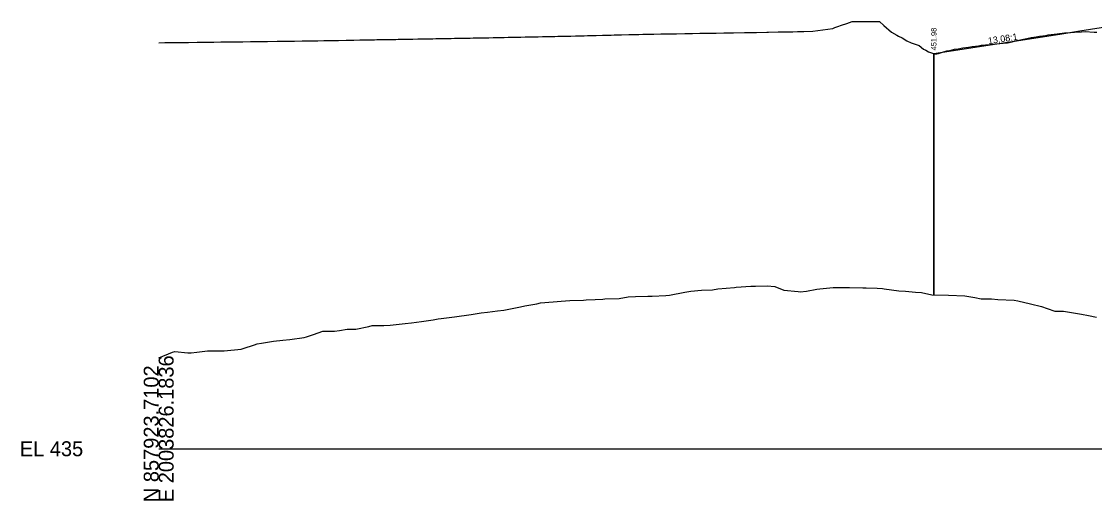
# Model space of a CAD drawing. Extents: x 2058594 to 2062449, y 841632 to 858028.
# Drawn here: x 2060920.8 to 2061121.7, y 856203.8 to 856293.5 of the extents above; entities that cross this region are included whole.
import ezdxf

# ---------------------------------------------------------------- set-up
doc = ezdxf.new("R2010")
doc.units = 0
for name, color, linetype in [('RD_DDB_Profile_Elev', 7, 'Continuous'), ('RD_GPK_XS_Cell', 7, 'Continuous'), ('RD_XS_EarthShd', 7, 'Continuous'), ('RD_XS_EwShp1', 7, 'Continuous'), ('RD_XS_ExGround', 7, 'Continuous'), ('RD_XS_MatchLine', 7, 'Continuous'), ('RD_XS_TieSlope', 7, 'Continuous'), ('RD_XS_TX_Ditch', 7, 'Continuous'), ('RD_XS_TX_Slope', 7, 'Continuous')]:
    doc.layers.add(name, color=color, linetype=linetype)

msp = doc.modelspace()

# ---------------------------------------------------------------- linework, layer by layer
at = {"layer": 'RD_DDB_Profile_Elev'}
msp.add_lwpolyline([(2060946.51, 856289.54), (2060947.67, 856289.56), (2060949.01, 856289.57), (2060950.54, 856289.59), (2060952.1, 856289.61), (2060953.74, 856289.63), (2060955.31, 856289.65), (2060956.81, 856289.67), (2060958.17, 856289.69), (2060959.34, 856289.7), (2060960.12, 856289.71), (2060961.06, 856289.72), (2060962.27, 856289.74), (2060963.68, 856289.75), (2060965.21, 856289.77), (2060966.89, 856289.79), (2060968.71, 856289.82), (2060970.37, 856289.84), (2060971.95, 856289.86), (2060973.39, 856289.88), (2060974.35, 856289.89), (2060975.33, 856289.9), (2060976.28, 856289.92), (2060977.42, 856289.94), (2060978.67, 856289.96), (2060980.16, 856289.99), (2060981.58, 856290.01), (2060982.73, 856290.03), (2060983.06, 856290.04), (2060984.16, 856290.06), (2060984.55, 856290.07), (2060985.57, 856290.09), (2060986, 856290.09), (2060986.91, 856290.11), (2060987.36, 856290.12), (2060988.12, 856290.13), (2060988.58, 856290.14), (2060989.15, 856290.15), (2060989.72, 856290.16), (2060990.18, 856290.17), (2060990.91, 856290.18), (2060991.33, 856290.19), (2060992.18, 856290.2), (2060992.55, 856290.21), (2060994.07, 856290.24), (2060995.04, 856290.25), (2060995.44, 856290.26), (2060996.4, 856290.28), (2060996.89, 856290.29), (2060997.82, 856290.3), (2060998.38, 856290.31), (2060999.24, 856290.33), (2060999.86, 856290.34), (2061000.61, 856290.35), (2061001.27, 856290.36), (2061001.89, 856290.37), (2061002.37, 856290.38), (2061003.03, 856290.39), (2061003.51, 856290.4), (2061004.16, 856290.41), (2061004.8, 856290.43), (2061005.39, 856290.44), (2061006.15, 856290.45), (2061006.66, 856290.46), (2061007.49, 856290.47), (2061007.89, 856290.48), (2061008.29, 856290.49), (2061009.15, 856290.5), (2061009.69, 856290.52), (2061010.35, 856290.53), (2061011.19, 856290.54), (2061011.94, 856290.56), (2061012.74, 856290.57), (2061013.56, 856290.59), (2061014.29, 856290.6), (2061015.15, 856290.62), (2061015.78, 856290.63), (2061016.64, 856290.65), (2061017.15, 856290.66), (2061017.53, 856290.67), (2061018.36, 856290.69), (2061018.73, 856290.7), (2061019.51, 856290.71), (2061020, 856290.72), (2061020.67, 856290.74), (2061021.25, 856290.75), (2061021.76, 856290.76), (2061022.3, 856290.77), (2061022.92, 856290.79), (2061023.64, 856290.8), (2061024.55, 856290.83), (2061025.15, 856290.84), (2061026.19, 856290.86), (2061026.76, 856290.88), (2061027.89, 856290.91), (2061028.4, 856290.92), (2061029.59, 856290.95), (2061030.01, 856290.96), (2061031.21, 856290.99), (2061031.77, 856291), (2061033.16, 856291.03), (2061034.55, 856291.07), (2061035.73, 856291.1), (2061036.42, 856291.11), (2061037.12, 856291.12), (2061038.06, 856291.14), (2061039.21, 856291.16), (2061040.53, 856291.18), (2061041.96, 856291.21), (2061043.47, 856291.23), (2061044.99, 856291.26), (2061046.46, 856291.28), (2061047.82, 856291.31), (2061048.99, 856291.32), (2061049.89, 856291.34), (2061050.88, 856291.36), (2061052.3, 856291.38), (2061054.09, 856291.42), (2061056.17, 856291.45), (2061058.44, 856291.49), (2061060.36, 856291.53), (2061060.69, 856291.53), (2061062.46, 856291.56), (2061064, 856291.59), (2061065.24, 856291.61), (2061066.09, 856291.62), (2061066.49, 856291.63), (2061066.8, 856291.64), (2061067.28, 856291.65), (2061069, 856291.68), (2061072.74, 856292.23), (2061073.11, 856292.37), (2061073.63, 856292.56), (2061074.36, 856292.82), (2061075.32, 856293.16), (2061076.34, 856293.53), (2061077.13, 856293.53), (2061077.48, 856293.53), (2061078.43, 856293.53), (2061079.12, 856293.53), (2061079.74, 856293.53), (2061080.64, 856293.53), (2061081.43, 856293.53), (2061082.27, 856292.74), (2061083.72, 856291.53), (2061084.69, 856290.98), (2061085.01, 856290.8), (2061085.67, 856290.44), (2061086.6, 856289.93), (2061087.36, 856289.53), (2061087.74, 856289.41), (2061088.89, 856289.01), (2061089.69, 856288.37), (2061090.15, 856288.13), (2061090.6, 856287.87), (2061091.74, 856287.44), (2061092.19, 856287.48), (2061092.52, 856287.53), (2061093.05, 856287.69), (2061094.08, 856288.01), (2061094.45, 856288.05), (2061095.48, 856288.33), (2061096.19, 856288.41), (2061097.08, 856288.62), (2061098.09, 856288.72), (2061098.77, 856288.86), (2061100.01, 856288.97), (2061100.47, 856289.06), (2061102.08, 856289.22), (2061103.37, 856289.33), (2061104.61, 856289.44), (2061105.44, 856289.53), (2061106.29, 856289.72), (2061107.18, 856289.96), (2061107.52, 856290.01), (2061108.43, 856290.24), (2061109.05, 856290.32), (2061109.86, 856290.52), (2061110.78, 856290.63), (2061111.42, 856290.77), (2061112.59, 856290.91), (2061113.02, 856291), (2061114.74, 856291.22), (2061116.09, 856291.37), (2061117.2, 856291.47), (2061117.96, 856291.53), (2061119.26, 856291.59), (2061119.96, 856291.65), (2061121.63, 856291.53), (2061122.12, 856291.53)], dxfattribs=at)
at = {"layer": 'RD_GPK_XS_Cell'}
msp.add_line((2060946.51, 856213.53), (2061196.51, 856213.53), dxfattribs=at)
at = {"layer": 'RD_XS_EarthShd'}
msp.add_line((2061124.96, 856292.65), (2061118.96, 856291.69), dxfattribs=at)
at = {"layer": 'RD_XS_EwShp1'}
for p, q in [((2061118.96, 856291.69), (2061115.21, 856291.09)), ((2061124.96, 856292.65), (2061118.96, 856291.69)), ((2061115.21, 856291.09), (2061091.62, 856287.48)), ((2061091.62, 856287.48), (2061091.62, 856242.33))]:
    msp.add_line(p, q, dxfattribs=at)
at = {"layer": 'RD_XS_ExGround'}
msp.add_lwpolyline([(2060946.51, 856230.55), (2060949.11, 856231.6), (2060949.52, 856231.75), (2060951.94, 856231.46), (2060952.6, 856231.5), (2060953.66, 856231.6), (2060955.68, 856231.89), (2060957.68, 856231.88), (2060958.76, 856231.89), (2060961.93, 856232.18), (2060962.3, 856232.32), (2060964.43, 856232.99), (2060964.93, 856233.16), (2060965.73, 856233.32), (2060968.01, 856233.7), (2060969.75, 856233.86), (2060971.09, 856234.01), (2060973.77, 856234.38), (2060974.17, 856234.46), (2060975.49, 856234.94), (2060977.25, 856235.55), (2060979.41, 856235.53), (2060980.33, 856235.64), (2060981.81, 856235.92), (2060983.41, 856235.92), (2060985.83, 856236.39), (2060986.49, 856236.59), (2060988.68, 856236.62), (2060989.85, 856236.65), (2060992.66, 856236.96), (2060993.87, 856237.11), (2060995.74, 856237.34), (2060997.89, 856237.64), (2060998.82, 856237.84), (2060999.4, 856237.91), (2061001.91, 856238.25), (2061004.98, 856238.69), (2061006.89, 856238.95), (2061008.06, 856239.08), (2061009.95, 856239.33), (2061011.15, 856239.49), (2061014.23, 856240.09), (2061015.05, 856240.27), (2061017.31, 856240.69), (2061018, 856240.83), (2061020.39, 856241.01), (2061021.88, 856241.14), (2061023.47, 856241.29), (2061026.04, 856241.33), (2061026.55, 856241.39), (2061028.24, 856241.45), (2061029.63, 856241.54), (2061030.06, 856241.58), (2061032.72, 856241.67), (2061034.37, 856241.95), (2061035.8, 856242.06), (2061038.1, 856242.09), (2061038.88, 856242.08), (2061041.43, 856242.23), (2061042.12, 856242.28), (2061045.04, 856242.82), (2061046.14, 856243.02), (2061048.12, 856243.19), (2061050.16, 856243.31), (2061051.2, 856243.49), (2061054.28, 856243.73), (2061054.61, 856243.76), (2061057.37, 856243.97), (2061058.21, 856243.99), (2061060.45, 856244.06), (2061061.84, 856243.89), (2061063.53, 856243.23), (2061066.25, 856242.95), (2061066.61, 856242.91), (2061067.8, 856243.06), (2061069.69, 856243.4), (2061070.27, 856243.48), (2061072.77, 856243.74), (2061074.33, 856243.74), (2061075.85, 856243.69), (2061078.31, 856243.66), (2061078.94, 856243.67), (2061080.99, 856243.57), (2061082.02, 856243.51), (2061082.33, 856243.47), (2061085.1, 856243.08), (2061086.35, 856243.02), (2061088.18, 856242.82), (2061089.32, 856242.76), (2061091.26, 856242.33), (2061094.39, 856242.28), (2061097.42, 856242.13), (2061099.31, 856241.84), (2061100.51, 856241.57), (2061102.43, 856241.58), (2061103.59, 856241.5), (2061106.67, 856241.36), (2061107.36, 856241.23), (2061109.75, 856240.67), (2061111.8, 856240.19), (2061112.83, 856239.78), (2061114.29, 856239.32), (2061115.91, 856239.32), (2061118.52, 856238.84), (2061119.29, 856238.72), (2061120.55, 856238.47), (2061122.07, 856238.19)], dxfattribs=at)
at = {"layer": 'RD_XS_MatchLine'}
msp.add_line((2061091.62, 856242.33), (2061091.62, 856287.48), dxfattribs=at)
at = {"layer": 'RD_XS_TieSlope'}
for p, q in [((2061118.96, 856291.69), (2061115.21, 856291.09)), ((2061115.21, 856291.09), (2061091.62, 856287.48))]:
    msp.add_line(p, q, dxfattribs=at)

# ---------------------------------------------------------------- texts
at = {"layer": 'RD_GPK_XS_Cell'}
for s, p in [('E 2003826.1836', (2060949.31, 856203.53)), ('N 857923.7102', (2060946.51, 856203.53))]:
    msp.add_text(s, height=2.8, rotation=90, dxfattribs=at).set_placement(p)
msp.add_text('EL 435', height=2.8, dxfattribs=at).set_placement((2060920.51, 856212.13))
at = {"layer": 'RD_XS_TX_Ditch'}
msp.add_text('451.98', height=1, rotation=90, dxfattribs=at).set_placement((2061092.12, 856288.12))
at = {"layer": 'RD_XS_TX_Slope'}
msp.add_text('13.08:1', height=1.25, rotation=8.6931, dxfattribs=at).set_placement((2061101.86, 856289.26))

doc.saveas('drawing.dxf')
